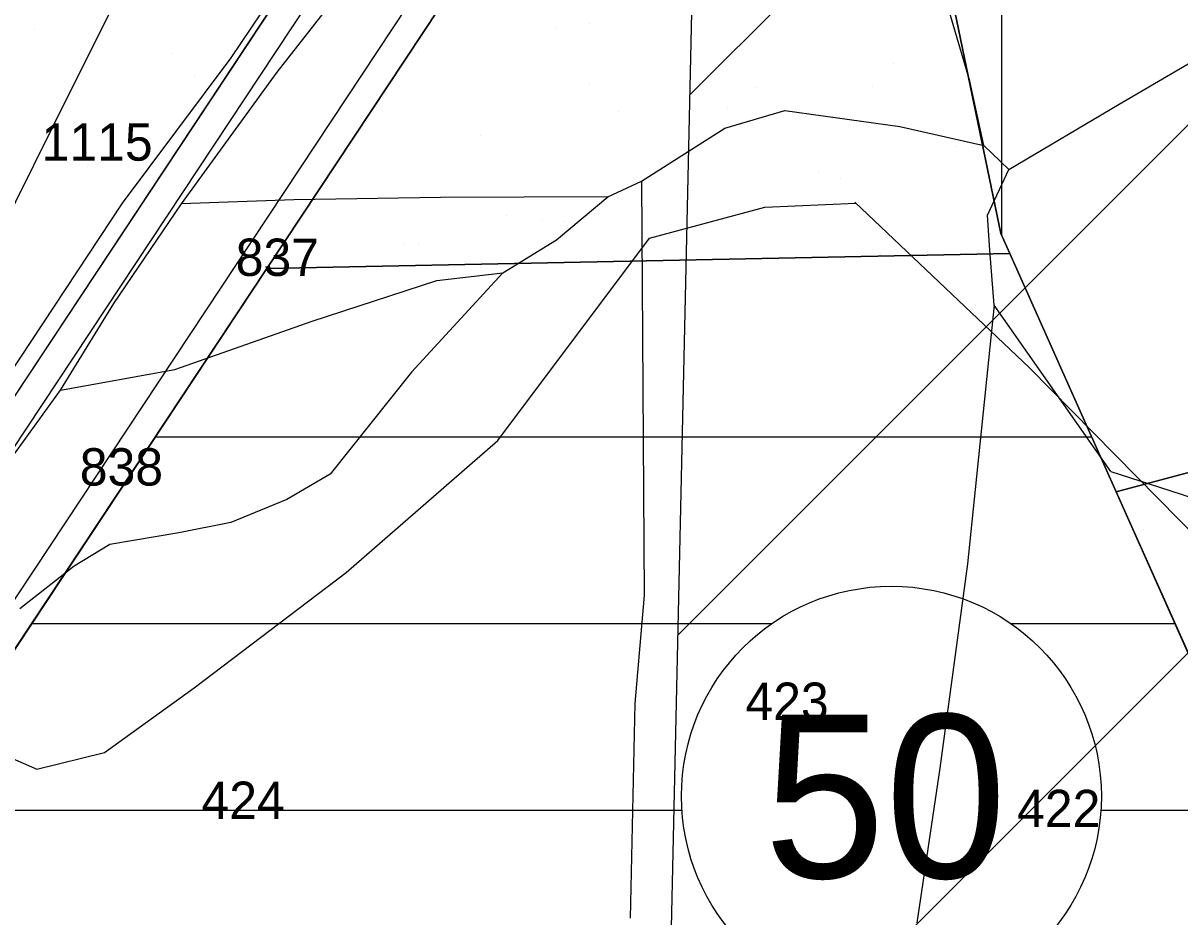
# Model space of a CAD drawing. Extents: x 410727 to 412947, y 4463506 to 4466382.
# Drawn here: x 410944.2 to 411068.2, y 4466174.6 to 4466270.3 of the extents above; entities that cross this region are included whole.
import ezdxf

# ---------------------------------------------------------------- set-up
doc = ezdxf.new("R2010")
doc.units = 0
for name, color, linetype in [('ADAKENARI', 7, 'Continuous'), ('KALDIRIM', 7, 'Continuous'), ('KDS_PARSEL_NO', 7, 'Continuous'), ('KDS_PL', 7, 'Continuous'), ('PL_AYA_PARK_DINLENME', 7, 'Continuous'), ('PL_KON_MEV_050', 7, 'Continuous'), ('PL_KON_ONE_50', 7, 'Continuous'), ('sembol', 7, 'Continuous'), ('SNR_KOYLER', 7, 'Continuous'), ('SNR_TR_AZGELISME', 7, 'Continuous'), ('TR_AZYOGUNLUK_MESKUN', 7, 'Continuous'), ('TR_GELİŞME_KONUT_ÇOKAZ', 7, 'Continuous'), ('TR_PARKALANI', 7, 'Continuous'), ('Yerlesime_uygunluk_sınırı', 7, 'Continuous')]:
    doc.layers.add(name, color=color, linetype=linetype)

msp = doc.modelspace()

# ---------------------------------------------------------------- linework, layer by layer
at = {"layer": 'ADAKENARI'}
for p, q in [((410984.87, 4466293.13), (410937.01, 4466220.86)), ((410970.35, 4466244.04), (411049.97, 4466245.63)), ((411049.97, 4466245.63), (411061.36, 4466220.11)), ((410934.05, 4466189.23), (410970.35, 4466244.04)), ((411061.36, 4466220.11), (411071.88, 4466196.56))]:
    msp.add_line(p, q, dxfattribs=at)
for points in [[(411192.1, 4466326.6), (411199.04, 4466311.27), (411191.3, 4466278.41), (411195.67, 4466251.72), (411191.89, 4466226.13), (411190.31, 4466188.93), (411154.6, 4466192.84), (411154.89, 4466194.74), (411133.79, 4466195.19), (411131.16, 4466218.16), (411125.23, 4466237.12), (411061.36, 4466220.11), (411049.97, 4466245.63), (411049.01, 4466247.79), (411036.24, 4466309.36), (411050.41, 4466319.17), (411055.74, 4466328.2)], [(410994.47, 4466280.46), (411036.24, 4466309.36), (411049.01, 4466247.79), (411049.97, 4466245.63), (410970.35, 4466244.04), (410994.47, 4466280.46)], [(411071.88, 4466196.56), (411061.36, 4466220.11), (411125.23, 4466237.12), (411131.16, 4466218.16), (411135.74, 4466178.25), (411069.2, 4466174.92), (411071.88, 4466196.56)]]:
    msp.add_lwpolyline(points, dxfattribs=at)
at = {"layer": 'KALDIRIM'}
msp.add_lwpolyline([(410877.26, 4466132.92), (410902.91, 4466163.94), (410984.73, 4466287.49), (410992.24, 4466282.52), (410910.15, 4466158.57), (410883.93, 4466126.86)], dxfattribs=at)
at = {"layer": 'KDS_PL'}
for p, q in [((410966.52, 4466266.61), (410977.39, 4466282.71)), ((410958.96, 4466282.37), (410947.29, 4466258.94)), ((410971.47, 4466265.05), (410982.7, 4466279.49)), ((411045.67, 4466264.11), (411043.25, 4466272.34)), ((411061.68, 4466261.62), (411076.14, 4466270.08)), ((410954.9, 4466251.01), (410966.52, 4466266.61)), ((410961.21, 4466250.96), (410971.47, 4466265.05)), ((411047.18, 4466257.19), (411045.67, 4466264.11)), ((411049.85, 4466254.64), (411061.68, 4466261.62)), ((411019.42, 4466259.06), (411025.86, 4466260.96)), ((411025.86, 4466260.96), (411038.17, 4466259.25)), ((411010.52, 4466253.37), (411019.42, 4466259.06)), ((411038.17, 4466259.25), (411047.18, 4466257.19)), ((410947.29, 4466258.94), (410941.14, 4466246.62)), ((411049.85, 4466254.64), (411047.18, 4466257.19)), ((411047.58, 4466249.75), (411049.85, 4466254.64)), ((411006.9, 4466251.7), (411010.52, 4466253.37)), ((411010.52, 4466253.37), (411010.78, 4466209.03)), ((410988.97, 4466251.63), (410973.25, 4466251.37)), ((411006.9, 4466251.7), (410988.97, 4466251.63)), ((411001.38, 4466247.11), (411006.9, 4466251.7)), ((410935.37, 4466221.54), (410954.9, 4466251.01)), ((410953.97, 4466240.29), (410961.21, 4466250.96)), ((410973.25, 4466251.37), (410961.21, 4466250.96)), ((411047.82, 4466245.98), (411047.58, 4466249.75)), ((410995.66, 4466243.56), (411001.38, 4466247.11)), ((411048.28, 4466240.11), (411047.82, 4466245.98)), ((410995.66, 4466243.56), (410985.85, 4466232.92)), ((410988.58, 4466242.75), (410995.66, 4466243.56)), ((410975.22, 4466238.38), (410988.58, 4466242.75)), ((410948.25, 4466231), (410953.97, 4466240.29)), ((411048.28, 4466240.11), (411045.45, 4466212.37)), ((411060.78, 4466222.27), (411048.28, 4466240.11)), ((410960.51, 4466233.19), (410975.22, 4466238.38)), ((410948.25, 4466231), (410960.51, 4466233.19)), ((410985.85, 4466232.92), (410977.13, 4466221.99)), ((410941.71, 4466221.99), (410948.25, 4466231)), ((410977.13, 4466221.99), (410972.5, 4466219.26)), ((411060.78, 4466222.27), (411066.01, 4466220.58)), ((411066.01, 4466220.58), (411081.43, 4466215.64)), ((410972.5, 4466219.26), (410966.5, 4466216.81)), ((410960.93, 4466215.71), (410953.52, 4466214.47)), ((410966.5, 4466216.81), (410960.93, 4466215.71)), ((410953.52, 4466214.47), (410949.7, 4466212.12)), ((410949.7, 4466212.12), (410943.9, 4466207.55)), ((411045.45, 4466212.37), (411042.48, 4466190.49)), ((411010.78, 4466209.03), (411009.79, 4466197.41)), ((411009.79, 4466197.41), (411009.29, 4466174.42)), ((411042.48, 4466190.49), (411040.02, 4466173.92))]:
    msp.add_line(p, q, dxfattribs=at)
at = {"layer": 'PL_AYA_PARK_DINLENME'}
for points in [[(410966.77, 4466329.24), (410952.62, 4466329.41), (410948.75, 4466326.83), (410945.69, 4466329.49), (410864.92, 4466330.44), (410865.03, 4466330.16), (410905.8, 4466318.77), (410931.26, 4466291.1), (410937.01, 4466220.86), (410984.87, 4466293.13), (410984.62, 4466304.63), (410966.77, 4466329.24)], [(410994.47, 4466280.46), (410970.35, 4466244.04), (411049.97, 4466245.63), (411049.01, 4466247.79), (411036.24, 4466309.36), (410994.47, 4466280.46)], [(411133.79, 4466195.19), (411131.16, 4466218.16), (411125.23, 4466237.12), (411061.36, 4466220.11), (411071.88, 4466196.56), (411069.2, 4466174.92), (411135.74, 4466178.25), (411133.79, 4466195.19)]]:
    msp.add_lwpolyline(points, dxfattribs=at)
at = {"layer": 'PL_KON_MEV_050'}
msp.add_lwpolyline([(411192.1, 4466326.6), (411055.74, 4466328.2), (411050.41, 4466319.17), (411036.24, 4466309.36), (411049.01, 4466247.79), (411049.97, 4466245.63), (411058.74, 4466226), (411061.36, 4466220.11), (411125.23, 4466237.12), (411131.16, 4466218.16), (411133.79, 4466195.19), (411154.89, 4466194.74), (411154.6, 4466192.84), (411190.31, 4466188.93), (411191.89, 4466226.13), (411195.67, 4466251.72), (411191.3, 4466278.41), (411199.04, 4466311.27), (411192.1, 4466326.6)], dxfattribs=at)
at = {"layer": 'PL_KON_ONE_50'}
msp.add_lwpolyline([(411018.73, 4466159.08), (411019.64, 4466094.39), (411040.6, 4466094.16), (411083.21, 4466088.38), (411127.43, 4466096.15), (411139.34, 4466102.02), (411143.99, 4466106.28), (411135.74, 4466178.25), (411069.2, 4466174.92), (411071.88, 4466196.56), (411061.36, 4466220.11), (411049.97, 4466245.63), (410970.35, 4466244.04), (410934.05, 4466189.23), (410938.28, 4466153.9), (410984.99, 4466158.37), (411018.73, 4466159.08)], dxfattribs=at)
at = {"layer": 'sembol'}
msp.add_circle((411037.28, 4466187.48), 22.5, dxfattribs=at)
at = {"layer": 'SNR_KOYLER'}
msp.add_line((411016.4, 4466295.47), (411011.82, 4466089.82), dxfattribs=at)
at = {"layer": 'SNR_TR_AZGELISME'}
for p, q in [((411014.38, 4466204.73), (411136.89, 4466327.25)), ((411015.66, 4466262.59), (411080.98, 4466327.9)), ((411013.09, 4466146.88), (411192.81, 4466326.59))]:
    msp.add_line(p, q, dxfattribs=at)
at = {"layer": 'TR_AZYOGUNLUK_MESKUN'}
msp.add_line((411049.1, 4466247.57), (411049.1, 4466318.27), dxfattribs=at)
msp.add_lwpolyline([(411055.74, 4466328.2), (411050.41, 4466319.17), (411036.24, 4466309.36), (411049.01, 4466247.79), (411049.97, 4466245.63), (411058.74, 4466226), (411061.36, 4466220.11), (411125.23, 4466237.12), (411131.16, 4466218.16), (411133.79, 4466195.19), (411154.89, 4466194.74), (411154.6, 4466192.84), (411190.31, 4466188.93), (411191.89, 4466226.13), (411195.67, 4466251.72), (411191.3, 4466278.41), (411199.04, 4466311.27), (411192.1, 4466326.6)], dxfattribs=at)
at = {"layer": 'TR_GELİŞME_KONUT_ÇOKAZ'}
for p, q in [((410958.4, 4466226), (411058.74, 4466226)), ((410945.16, 4466206), (411024.49, 4466206)), ((411050.06, 4466206), (411067.66, 4466206)), ((410934.44, 4466186), (411014.83, 4466186)), ((411059.73, 4466186), (411070.57, 4466186))]:
    msp.add_line(p, q, dxfattribs=at)
at = {"layer": 'TR_PARKALANI'}
for p, q in [((411004.9, 4466270.23), (411004.9, 4466270.23)), ((411004.9, 4466270.23), (411004.9, 4466270.23)), ((410945.48, 4466269.63), (410945.48, 4466269.63)), ((410945.48, 4466269.63), (410945.48, 4466269.63)), ((410945.48, 4466269.63), (410945.48, 4466269.63)), ((411001.35, 4466269.81), (411001.35, 4466269.81)), ((411001.35, 4466269.81), (411001.35, 4466269.81)), ((410960.26, 4466267.02), (410960.26, 4466267.02)), ((410960.26, 4466267.02), (410960.26, 4466267.02)), ((410960.26, 4466267.02), (410960.26, 4466267.02)), ((410986.57, 4466267.21), (410986.57, 4466267.21)), ((410986.57, 4466267.21), (410986.57, 4466267.21)), ((411037.55, 4466266.04), (411037.55, 4466266.04)), ((411037.55, 4466266.04), (411037.55, 4466266.04)), ((410962.62, 4466264.62), (410962.62, 4466264.62)), ((410962.62, 4466264.62), (410962.62, 4466264.62)), ((410962.62, 4466264.62), (410962.62, 4466264.62)), ((411004.89, 4466263.83), (411004.89, 4466263.83)), ((411022.78, 4466263.44), (411022.78, 4466263.44)), ((411022.78, 4466263.44), (411022.78, 4466263.44)), ((411035.31, 4466263.54), (411035.31, 4466263.54)), ((411008.01, 4466260.83), (411008.01, 4466260.83)), ((411008.01, 4466260.83), (411008.01, 4466260.83)), ((411019.67, 4466261.22), (411019.67, 4466261.22)), ((410949.76, 4466259.66), (410949.76, 4466259.66)), ((410949.76, 4466259.66), (410949.76, 4466259.66)), ((410949.76, 4466259.66), (410949.76, 4466259.66)), ((410949.76, 4466259.66), (410949.76, 4466259.66)), ((410949.76, 4466259.66), (410949.76, 4466259.66)), ((410949.76, 4466259.66), (410949.76, 4466259.66)), ((410993.23, 4466258.23), (410993.23, 4466258.23)), ((410993.23, 4466258.23), (410993.23, 4466258.23)), ((411044.21, 4466257.06), (411044.21, 4466257.06)), ((411044.21, 4466257.06), (411044.21, 4466257.06)), ((410978.46, 4466255.62), (410978.46, 4466255.62)), ((410978.46, 4466255.62), (410978.46, 4466255.62)), ((410951.13, 4466254.98), (410951.13, 4466254.98)), ((410951.13, 4466254.98), (410951.13, 4466254.98)), ((410951.13, 4466254.98), (410951.13, 4466254.98)), ((410951.13, 4466254.98), (410951.13, 4466254.98)), ((410951.13, 4466254.98), (410951.13, 4466254.98)), ((410951.13, 4466254.98), (410951.13, 4466254.98)), ((411029.44, 4466254.46), (411029.44, 4466254.46)), ((411029.44, 4466254.46), (411029.44, 4466254.46)), ((411031.84, 4466253.68), (411031.84, 4466253.68)), ((411014.67, 4466251.85), (411014.67, 4466251.85)), ((411014.67, 4466251.85), (411014.67, 4466251.85)), ((410956.42, 4466250.68), (410956.42, 4466250.68)), ((410956.42, 4466250.68), (410956.42, 4466250.68)), ((410956.42, 4466250.68), (410956.42, 4466250.68)), ((410956.42, 4466250.68), (410956.42, 4466250.68)), ((410956.42, 4466250.68), (410956.42, 4466250.68)), ((410956.42, 4466250.68), (410956.42, 4466250.68)), ((410996, 4466249.72), (410996, 4466249.72)), ((410999.89, 4466249.25), (410999.89, 4466249.25)), ((410999.89, 4466249.25), (410999.89, 4466249.25)), ((411002.29, 4466249.05), (411002.29, 4466249.05)), ((410986.65, 4466246.74), (410986.65, 4466246.74)), ((410985.12, 4466246.64), (410985.12, 4466246.64)), ((410985.12, 4466246.64), (410985.12, 4466246.64)), ((411036.1, 4466245.48), (411036.1, 4466245.48)), ((411036.1, 4466245.48), (411036.1, 4466245.48)), ((410948.31, 4466239.1), (410948.31, 4466239.1)), ((410948.31, 4466239.1), (410948.31, 4466239.1)), ((410948.31, 4466239.1), (410948.31, 4466239.1)), ((410948.31, 4466239.1), (410948.31, 4466239.1)), ((410948.31, 4466239.1), (410948.31, 4466239.1)), ((410948.31, 4466239.1), (410948.31, 4466239.1)), ((411064.26, 4466216.05), (411064.26, 4466216.05)), ((411064.26, 4466216.05), (411064.26, 4466216.05))]:
    msp.add_line(p, q, dxfattribs=at)
at = {"layer": 'Yerlesime_uygunluk_sınırı'}
for points in [[(410933.38, 4466195.79), (410945.72, 4466190.37), (410952.95, 4466192.18), (410962.58, 4466199.1), (410978.84, 4466211.45), (410995.1, 4466225.6), (411011.36, 4466247.28), (411023.71, 4466250.6), (411033.48, 4466251.04)], [(411033.37, 4466251.15), (411052.08, 4466233.4), (411070.42, 4466214.78), (411078.49, 4466206.71), (411091.27, 4466210.88), (411103.78, 4466215.33), (411117.68, 4466216.72), (411129.91, 4466214.5), (411147.98, 4466213.94), (411170.21, 4466218.11), (411193, 4466222.28), (411218.58, 4466224.23), (411238.31, 4466223.67), (411259.99, 4466227.84)]]:
    msp.add_lwpolyline(points, dxfattribs=at)

# ---------------------------------------------------------------- texts
at = {"layer": 'KDS_PARSEL_NO'}
for s, p in [('1115', (410946.22, 4466255.58)), ('837', (410967.02, 4466243.23)), ('838', (410950.31, 4466220.77)), ('423', (411021.64, 4466195.66)), ('424', (410963.35, 4466185.05)), ('422', (411050.75, 4466184.17))]:
    msp.add_text(s, height=4, dxfattribs=at).set_placement(p)
at = {"layer": 'sembol'}
msp.add_text('50', height=17.5, dxfattribs=at).set_placement((411023.61, 4466178.73))

doc.saveas('drawing.dxf')
